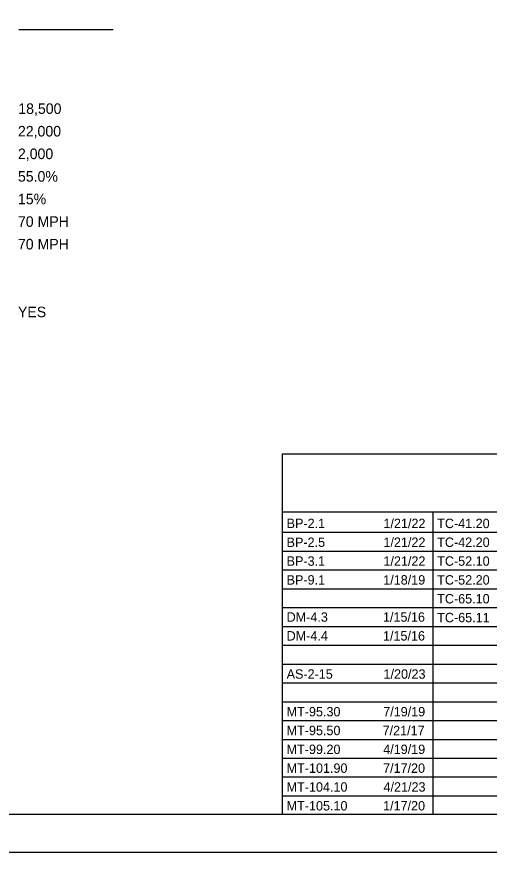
# Model space of a CAD drawing. Extents: x -14196 to 143, y -6096 to 28.
# Drawn here: x 7.72 to 14, y 0 to 11.1 of the extents above; entities that cross this region are included whole.
import ezdxf

# ---------------------------------------------------------------- set-up
doc = ezdxf.new("R2010")
doc.units = 0
for name, color, linetype in [('RS_Raster1', 7, 'Continuous'), ('SH_Border', 7, 'Continuous'), ('SH_Cut_Line', 7, 'Continuous'), ('SH_Data', 7, 'Continuous'), ('SH_Text', 7, 'Continuous')]:
    doc.layers.add(name, color=color, linetype=linetype)

msp = doc.modelspace()

# ---------------------------------------------------------------- linework, layer by layer
at = {"layer": 'RS_Raster1'}
msp.add_line((9, 10.922), (7.75, 10.922), dxfattribs=at)
at = {"layer": 'SH_Border'}
msp.add_lwpolyline([(1.5, 21.5), (33.5, 21.5), (33.5, 0.5), (1.5, 0.5)], close=True, dxfattribs=at)
at = {"layer": 'SH_Cut_Line'}
msp.add_lwpolyline([(0, 0), (34, 0), (34, 22), (0, 22)], close=True, dxfattribs=at)
at = {"layer": 'SH_Data'}
for p, q in [((11.25, 5.292), (24.7, 5.292)), ((11.25, 0.5), (11.25, 5.292)), ((11.25, 4.521), (24.7, 4.521)), ((13.25, 0.5), (13.25, 4.521)), ((11.25, 4.25), (24.7, 4.25)), ((11.25, 4), (24.7, 4)), ((11.25, 3.75), (24.7, 3.75)), ((11.25, 3.5), (24.7, 3.5)), ((11.25, 3.25), (24.7, 3.25)), ((11.25, 3), (24.7, 3)), ((11.25, 2.75), (24.7, 2.75)), ((11.25, 2.5), (24.7, 2.5)), ((11.25, 2.25), (24.7, 2.25)), ((11.25, 2), (24.7, 2)), ((11.25, 1.75), (24.7, 1.75)), ((11.25, 1.5), (24.7, 1.5)), ((11.25, 1.25), (24.7, 1.25)), ((11.25, 1), (24.7, 1)), ((11.25, 0.75), (24.7, 0.75))]:
    msp.add_line(p, q, dxfattribs=at)

# ---------------------------------------------------------------- texts
at = {"layer": 'RS_Raster1'}
for s, p in [('18,500', (7.742, 9.806)), ('22,000', (7.737, 9.506)), ('2,000 ', (7.737, 9.206)), ('55.0% ', (7.737, 8.906)), ('15%   ', (7.737, 8.606)), ('70 MPH', (7.737, 8.306)), ('70 MPH', (7.737, 8.006)), ('YES   ', (7.737, 7.106))]:
    msp.add_text(s, height=0.14, dxfattribs=at).set_placement(p)
at = {"layer": 'SH_Text'}
for s, p in [('BP-2.1', (11.305, 4.305)), ('1/21/22', (12.591, 4.305)), ('TC-41.20', (13.305, 4.305)), ('BP-2.5', (11.305, 4.055)), ('1/21/22', (12.591, 4.055)), ('TC-42.20', (13.305, 4.055)), ('BP-3.1', (11.305, 3.805)), ('1/21/22', (12.591, 3.805)), ('TC-52.10', (13.305, 3.805)), ('BP-9.1', (11.305, 3.555)), ('1/18/19', (12.588, 3.555)), ('TC-52.20', (13.305, 3.555)), ('TC-65.10', (13.305, 3.305)), ('DM-4.3', (11.305, 3.062)), ('1/15/16', (12.585, 3.062)), ('TC-65.11', (13.305, 3.055)), ('DM-4.4', (11.305, 2.812)), ('1/15/16', (12.585, 2.812)), ('AS-2-15', (11.305, 2.305)), ('1/20/23', (12.592, 2.305)), ('MT-95.30', (11.305, 1.805)), ('7/19/19', (12.588, 1.805)), ('MT-95.50', (11.305, 1.555)), ('7/21/17', (12.58, 1.555)), ('MT-99.20', (11.305, 1.305)), ('4/19/19', (12.588, 1.305)), ('MT-101.90', (11.305, 1.055)), ('7/17/20', (12.586, 1.055)), ('MT-104.10', (11.305, 0.805)), ('4/21/23', (12.592, 0.805)), ('MT-105.10', (11.305, 0.555)), ('1/17/20', (12.586, 0.555))]:
    msp.add_text(s, height=0.125, dxfattribs=at).set_placement(p)

doc.saveas('drawing.dxf')
